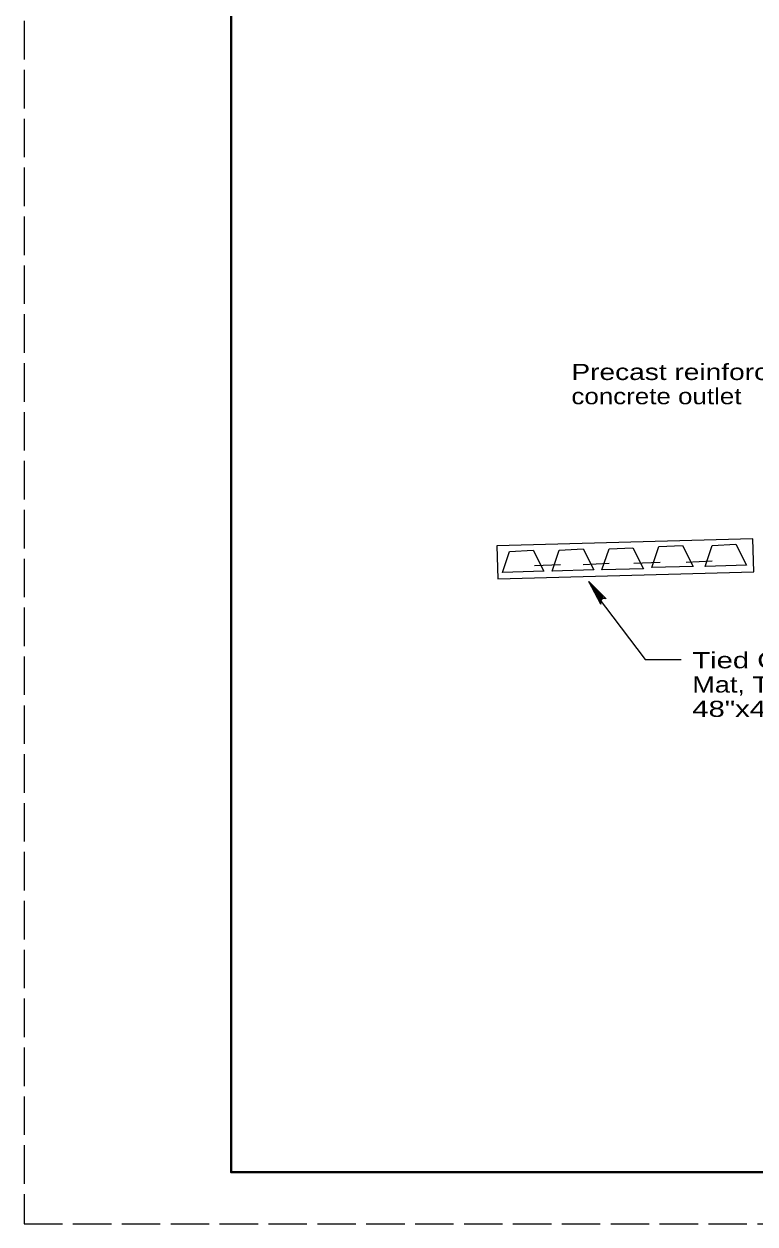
# Model space of a CAD drawing. Extents: x 1083.1 to 1117.1, y 697.4 to 741.4.
# Drawn here: x 1083.13 to 1090.18, y 697.35 to 708.94 of the extents above; entities that cross this region are included whole.
import ezdxf

# ---------------------------------------------------------------- set-up
doc = ezdxf.new("R2010")
doc.units = 0
doc.header["$LTSCALE"] = 0.062
doc.linetypes.add('LONG_DASHED', pattern=[7.5, 6, -1.5])
doc.layers.add('1', color=7, linetype='Continuous', lineweight=13)

msp = doc.modelspace()

# ---------------------------------------------------------------- linework, layer by layer
at = {"layer": '1'}
for p, q in [((1088.05417, 703.71175), (1088.30592, 703.72317)), ((1088.52333, 703.72325), (1088.77508, 703.73467)), ((1089.01533, 703.73467), (1089.26708, 703.74608)), ((1089.51875, 703.74608), (1089.7705, 703.7575)), ((1088.70308, 703.38275), (1088.57892, 703.55883)), ((1088.69425, 703.36975), (1088.57892, 703.55883)), ((1088.69092, 703.35733), (1088.57892, 703.55883)), ((1088.71292, 703.38992), (1088.57892, 703.55883)), ((1088.72542, 703.39417), (1088.57892, 703.55883))]:
    msp.add_line(p, q, dxfattribs=at)
at = {"layer": '1', "linetype": 'LONG_DASHED'}
msp.add_lwpolyline([(1083.12642, 697.35408), (1117.12642, 697.35408), (1117.12642, 719.35408), (1083.12642, 719.35408)], close=True, dxfattribs=at)
at = {"layer": '1', "lineweight": 25}
msp.add_lwpolyline([(1116.62642, 697.85408), (1085.12642, 697.85408), (1085.12642, 718.85408)], dxfattribs=at)
at = {"layer": '1', "lineweight": 40}
msp.add_lwpolyline([(1085.12642, 718.85408), (1116.62642, 718.85408), (1116.62642, 697.85408), (1085.12642, 697.85408)], close=True, dxfattribs=at)
msp.add_lwpolyline([(1085.12642, 718.85408), (1116.62642, 718.85408), (1116.62642, 697.85408), (1085.12642, 697.85408)], close=True, dxfattribs=at)
at = {"layer": '1', "lineweight": 25}
msp.add_lwpolyline([(1090.1615, 703.96867), (1087.69092, 703.90117), (1087.70117, 703.58417), (1090.17175, 703.65167)], close=True, dxfattribs=at)
at = {"layer": '1'}
for points in [[(1089.187, 703.69208), (1089.25567, 703.89483), (1089.4845, 703.90625), (1089.58742, 703.7035)], [(1089.70183, 703.70358), (1089.7705, 703.90633), (1089.99933, 703.91775), (1090.10225, 703.715)], [(1087.74525, 703.64633), (1087.81392, 703.84908), (1088.04275, 703.8605), (1088.14567, 703.65775)], [(1088.22575, 703.65775), (1088.29442, 703.8605), (1088.52325, 703.87192), (1088.62617, 703.66917)], [(1088.70633, 703.66925), (1088.775, 703.872), (1089.00383, 703.88342), (1089.10675, 703.68067)]]:
    msp.add_lwpolyline(points, close=True, dxfattribs=at)
for points in [[(1088.694, 703.33808), (1088.57892, 703.55883), (1088.74775, 703.39108)], [(1088.65958, 703.41492), (1089.12375, 702.80492), (1089.46983, 702.80492)]]:
    msp.add_lwpolyline(points, dxfattribs=at)
msp.add_arc((1088.73167, 703.35372), 0.04075, 66.65454, 202.48066, dxfattribs=at)

# ---------------------------------------------------------------- texts
for s, width, p in [('Precast reinforced', 1.3, (1088.41117, 705.50333)), ('concrete outlet', 1.2, (1088.41117, 705.26933)), ('Tied Concrete Block ', 1.35, (1089.57883, 702.71983)), ('Mat, Type 2, Grouted.', 1.25, (1089.57883, 702.48517)), ('48"x48" [1.2m x 1.2m] ', 1.35, (1089.57883, 702.2505))]:
    msp.add_text(s, height=0.156, dxfattribs=dict(at, width=width)).set_placement(p)

doc.saveas('drawing.dxf')
